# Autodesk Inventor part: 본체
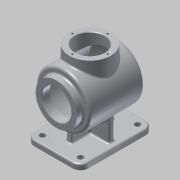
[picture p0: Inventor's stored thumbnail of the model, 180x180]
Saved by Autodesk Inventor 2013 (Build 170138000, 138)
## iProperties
Created: 2016-09
Part Number: 본체
Material: 알루미늄 6061
Document SubType Name: Modeling
Designer: Administrator
Mass: 941.493 g
Surface Area: 1328.18 cm^2
Volume: 347.415 cm^3
Density: 2.71 g/cm^3
Author: Administrator
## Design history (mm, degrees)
sketch "스케치3"
  geometry: C1 r 50 at (0, 0); 1 further point
  constraints: 1 centre point, 1 coincident
  dimensions: "d2" = 100 diameter of C1
extrude "돌출1" new body sketch "스케치3" distance "d4" = 110; taper "d5" = 0 deg
node "작업 평면1"
sketch "스케치4"
  geometry: L1 (0, 50)-(110, 50) reference; L2 (110, -50)-(110, 50) reference; L3 (0, 0)-(110, 0); A1 r 115 centre (-5, 0) between (110, 0) and (98.562, 50)
  constraints: 2 end point, 2 point on circle, 1 centre point, 1 midpoint, 1 point on line, 1 tangent
  dimensions: "d17" = 115 radius of A1
revolve "회전1" sketch "스케치4" stored, may be unused: angle "d19" = 90 deg
sketch "스케치5"
  geometry: C1 r 50 at (0, 0) reference; C2 r 38 at (0, 0)
  constraints: 1 centre point, 1 coincident
  dimensions: "d20" = 76 diameter of C2
extrude "돌출2" join sketch "스케치5" distance "d22" = 12; taper "d23" = 0 deg
sketch "스케치6"
  geometry: C1 r 38 at (0, 0) reference; C2 r 27 at (0, 0)
  constraints: 1 centre point, 1 coincident
  dimensions: "d24" = 54 diameter of C2
extrude "돌출3" cut sketch "스케치6" distance "d26" = 15; taper "d27" = 0 deg
feature "쉘1" dims "d28" = 3
node "작업 평면2"
sketch "스케치7"
  geometry: L1 (-50, 98.562)-(50, 98.562) reference; L2 (-50, 0)-(50, 0) reference; L3 (-38, -12)-(38, -12) reference; L4 (-50, 0)-(-50, 98.562) reference; L5 (50, 0)-(50, 98.562) reference; L6 (-50, 50)-(50, 50); C1 r 38 at (0, 50); A1 r 115 centre (0, -5) between (50, 98.562) and (-50, 98.562) reference; 1 further point
  constraints: 2 end point, 2 point on line, 1 centre point, 1 midpoint, 1 perpendicular
  dimensions: "d32" = 62 distance between parallel lines of L3 L6; "d33" = 76 diameter of C1
extrude "돌출4" join sketch "스케치7" stored distance "d34" = 15; taper "d35" = 0 deg
sketch "스케치8"
  geometry: C1 r 38 at (0, 0) reference; C2 r 27 at (0, 0); 1 further point
  constraints: 1 centre point, 1 coincident
  dimensions: "d36" = 54 diameter of C2
extrude "돌출5" cut sketch "스케치8" stored distance "d38" = 15; taper "d39" = 0 deg
node "작업 평면3"
sketch "스케치9"
  geometry: L1 (-38, -12)-(38, -12) reference; L2 (-50, 117.5)-(50, 117.5); L3 (50, 117.5)-(50, -17.5); L4 (50, -17.5)-(-50, -17.5); L5 (-50, -17.5)-(-50, 117.5); L6 (-50, 50)-(50, 50); L7 (0, -17.5)-(0, 117.5); 1 further point
  constraints: 12 end point, 4 midpoint, 2 parallel, 1 horizontal, 1 perpendicular
  dimensions: "d41" = 62 distance between parallel lines of L1 L6; "d42" = 135 distance between parallel lines of L4 L2; "d43" = 100 distance between parallel lines of L3 L5; "d44" = 0 distance from line of point (0, 0) L7
extrude "돌출6" join sketch "스케치9" distance "d45" = 10; taper "d46" = 0 deg
sketch "스케치10"
  geometry: L1 (50, 117.5)-(-50, 117.5) reference; L2 (-50, 117.5)-(-50, -17.5) reference; L3 (-50, -17.5)-(50, -17.5) reference; L4 (50, -17.5)-(50, 117.5) reference; L5 (-50, 50)-(50, 50); L6 (-40, 45)-(40, 45); L7 (40, 45)-(40, 55); L8 (40, 55)-(-40, 55); L9 (-40, 55)-(-40, 45); L10 (0, 117.5)-(0, -17.5); 1 further point
  constraints: 12 end point, 4 midpoint, 2 parallel, 1 horizontal, 1 perpendicular
  dimensions: "d61" = 5 distance between parallel lines of L5 L6; "d63" = 10 distance between parallel lines of L6 L8; "d64" = 40 distance between parallel lines of L7 L10; "d65" = 40 distance between parallel lines of L9 L10
extrude "돌출7" join sketch "스케치10" stored distance "d66" = 10; taper "d67" = 0 deg
node "작업 평면5"
sketch "스케치15" dims "d100" = 65
  geometry: C1 r 27 at (0, 0) reference; C2 r 38 at (0, 0) reference; C3 r 2 at (0, 32.5); 2 further points
  constraints: 2 vertical alignment, 1 centre point, 1 coincident, 2 other
  dimensions: "d102" = 4 diameter of C3
hole "구멍2" sketch "스케치15" at (0, 32.5) diameter "d103" = 3.242; stored, may be unused: countersink angle "d107" = 90 deg, drill point angle "d109" = 118 deg; dims "d104" = 8, "d105" = 4, "d106" = 2, "d108" = 10
node "작업 평면6"
sketch "스케치16"
  geometry: L1 (-29.035, 4.203)-(29.035, 4.203); L2 (29.035, 4.203)-(29.035, -4.203); L3 (29.035, -4.203)-(-29.035, -4.203); L4 (-29.035, -4.203)-(-29.035, 4.203); L5 (-29.035, 0)-(29.035, 0); L6 (0, 4.203)-(0, -4.203); 1 further point
  constraints: 4 end point, 4 midpoint, 2 other
  dimensions: "d114" = 0 distance from line of point (0, 0) L6; "d115" = 0 distance from line of point (0, 0) L5
feature "엠보싱1" sketch "스케치16" dims "d2" = 100, "d116" = 0.5, "d117" = 0
fillet "모깎기1" dims "d118" = 2
chamfer "모따기1" distance "d119" = 1; stored, may be unused: second distance "d120" = 2, angle "d121" = 45 deg
fillet "모깎기2" dims "d122" = 5
fillet "모깎기3" dims "d123" = 3
fillet "모깎기4" dims "d124" = 3
fillet "모깎기5" dims "d125" = 15
sketch "스케치17"
  geometry: C1 r 5 at (-35, -2.5); C2 r 5 at (-35, 102.5); C3 r 5 at (35, 102.5); C4 r 5 at (35, -2.5); A1 r 15 centre (-35, 102.5) between (-35, 117.5) and (-50, 102.5) reference; A2 r 15 centre (-35, -2.5) between (-50, -2.5) and (-35, -17.5) reference; A3 r 15 centre (35, -2.5) between (35, -17.5) and (50, -2.5) reference; A4 r 15 centre (35, 102.5) between (50, 102.5) and (35, 117.5) reference; 1 further point
  constraints: 4 centre point, 4 coincident, 3 equal radius
  dimensions: "d126" = 10 diameter of C1
extrude "돌출9" cut sketch "스케치17" stored distance "d128" = 10; taper "d129" = 0 deg
fillet "모깎기6" dims "d130" = 3
node "작업 평면7"
sketch "스케치18"
  geometry: L1 (12.187, -47)-(10, -72); L2 (-2.5, -72)-(102.5, -72) reference; L3 (5, -47)-(95.374, -47) reference; L4 (50, -47)-(50, -72); L5 (-12, 28)-(-12, -28) reference; L6 (12.187, -47)-(50, -47); 1 further point
  constraints: 6 end point, 2 point on line, 1 collinear, 1 midpoint, 1 perpendicular
  dimensions: "d132" = 0 distance from line of L2 L1.end; "d133" = 95 deg angle of L2 L1; "d134" = 62 distance between parallel lines of L5 L4; "d135" = 40 distance from line of L1.end L4
feature "리브1" sketch "스케치18" dims "d136" = 1, "d137" = 10, "d138" = 0, "d139" = 0, "d140" = 1, "d141" = 1
sketch "스케치19"
  geometry: L1 (5, -47)-(95.374, -47) reference; L2 (87.813, -47)-(90, -72); L3 (-12, 28)-(-12, -28) reference; L4 (-2.5, -72)-(102.5, -72) reference; L5 (50, -47)-(87.813, -47); L6 (50, -47)-(50, -72); 1 further point
  constraints: 6 end point, 2 point on line, 1 collinear, 1 midpoint
  dimensions: "d143" = 0 distance from line of L4 L2.end; "d144" = 95 deg angle of L4 L2; "d147" = 25 distance of L5.start L6.end; "d148" = 40 distance from line of L6 L2.end
feature "리브2" sketch "스케치19" dims "d149" = 1, "d150" = 10, "d151" = 0, "d152" = 0, "d153" = 1, "d154" = 1
fillet "모깎기7" dims "d155" = 3
fillet "모깎기8" dims "d156" = 3
sketch "스케치20"
  geometry: C1 r 30 at (0, 0) reference; C2 r 35 at (0, 0) reference
extrude "돌출10" join sketch "스케치20" stored distance "d157" = 10; taper "d158" = 0 deg
sketch "스케치21" dims "d159" = 65
  geometry: C1 r 38 at (0, 0) reference; C2 r 28 at (0, 0) reference; C3 r 2 at (0, 32.5); 1 further point
  constraints: 2 vertical alignment, 1 centre point, 1 coincident, 2 other
  dimensions: "d161" = 4 diameter of C3
hole "구멍3" sketch "스케치21" at (0, 32.5) diameter "d162" = 3.242; stored, may be unused: countersink angle "d166" = 90 deg, drill point angle "d168" = 118 deg; dims "d163" = 8, "d164" = 4, "d165" = 2, "d167" = 10
node "솔리드1"
pattern_circular "원형 패턴2" dims angle "d111" = 360 deg
pattern_circular "원형 패턴3" dims angle "d170" = 360 deg
node "투영된 루프1"
other parameters: "d6" = 0, "d29" = 65, "d40" = -82, "d77" = 0, "d113" = 229.5, "d131" = 0
